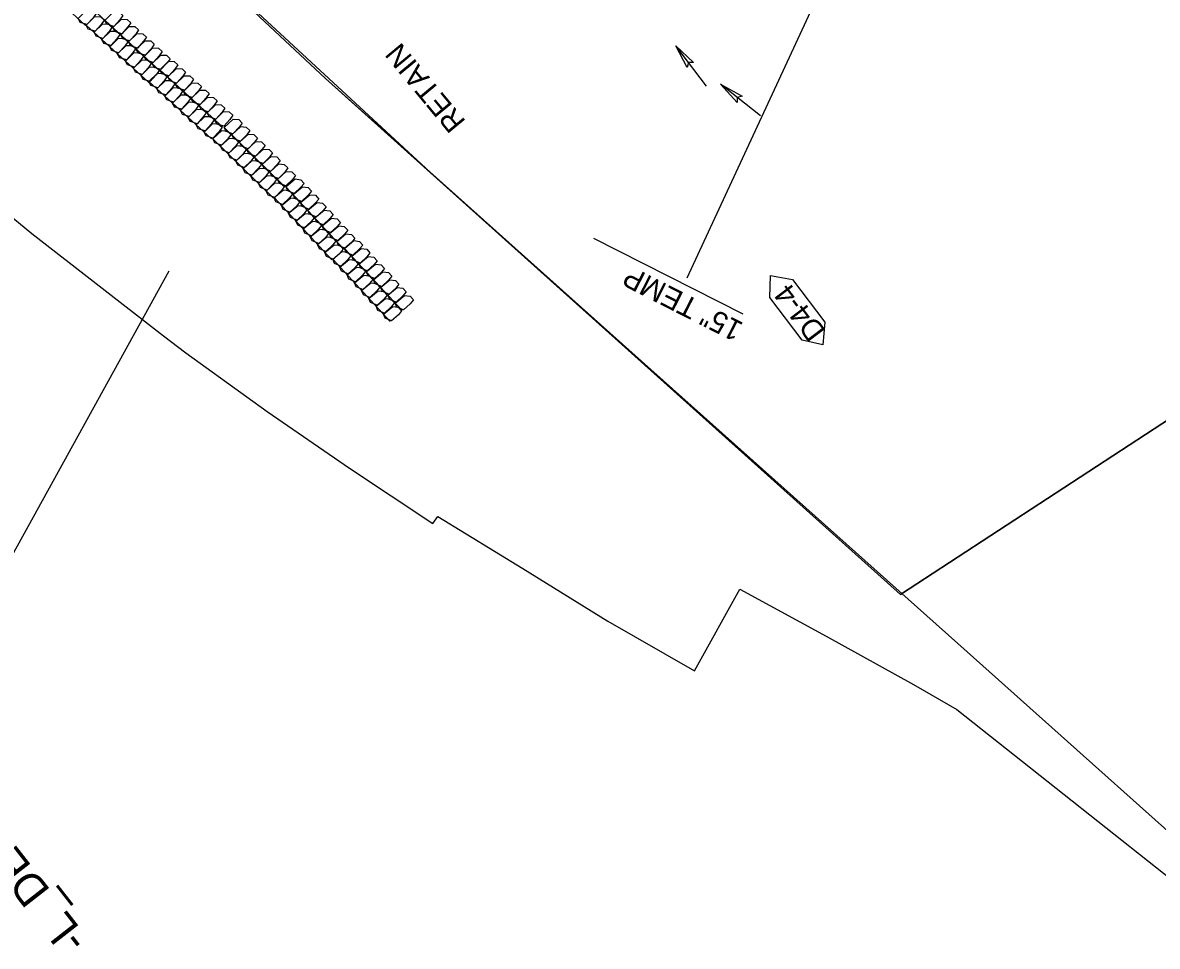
# Model space of a CAD drawing. Extents: x 465700 to 483515, y 488970 to 507540.
# Drawn here: x 476627.3 to 476894.9, y 500472.6 to 500690.3 of the extents above; entities that cross this region are included whole.
import ezdxf

# ---------------------------------------------------------------- set-up
doc = ezdxf.new("R2010")
doc.units = 0
for name, color, linetype in [('Exist Plan Preparation Watershed Blue', 7, 'Continuous'), ('Prop Drainage Structure Box Number Symbol CELL', 7, 'Continuous'), ('Prop Drainage Structure Pipe Collar Label', 7, 'Continuous'), ('Prop Drainage Structure Pipe Side Drain 15in', 7, 'Continuous'), ('Prop Drainage Structure Pipe Side Drain 15in Label', 7, 'Continuous'), ('Prop Erosion Embankment Toe Protection CELL', 7, 'Continuous'), ('Prop Plan Preparation Grade to Drain Arrows CELL', 7, 'Continuous'), ('Prop Plan Preparation Sag', 7, 'Continuous'), ('Prop Plan Preparation Sag Label', 7, 'Continuous')]:
    doc.layers.add(name, color=color, linetype=linetype)

msp = doc.modelspace()

# ---------------------------------------------------------------- linework, layer by layer
at = {"layer": 'Exist Plan Preparation Watershed Blue'}
for points in [[(476921.2, 501693.96), (476873.97, 501665.49), (476797.54, 501630.58), (476778.04, 501586.57), (476684.08, 501524.02), (476617.13, 501430.2), (476608.09, 501344.67), (476632.2, 501297.34), (476652.85, 501202.84), (476684.48, 501113.94), (476686.07, 501079.86), (476666.3, 501048.93), (476630.01, 501028.21), (476577.87, 501021.26), (476528.03, 501006.59), (476466.6, 500992.22), (476420.26, 500966.99), (476486.96, 500889.51), (476555.03, 500816.27), (476625.62, 500745.44), (476698.65, 500677.13), (476726.48, 500652.21), (476834.31, 500555.52), (476965.29, 500641)], [(476922.43, 500477.32), (476847.82, 500543.91), (476773.22, 500610.51), (476698.65, 500677.13), (476625.62, 500745.44), (476555.03, 500816.27), (476486.96, 500889.51), (476420.26, 500966.99), (476358.7, 501042.92), (476298.67, 501122.89), (476241.47, 501204.91)], [(476965.29, 500641), (476834.31, 500555.52), (476726.48, 500652.21), (476625.62, 500745.44), (476555.03, 500816.27), (476486.96, 500889.51), (476420.26, 500966.99), (476358.7, 501042.92), (476298.67, 501122.89), (476241.47, 501204.91)], [(476537.67, 500723.12), (476574.27, 500687.93), (476600.68, 500664.31), (476629.44, 500640.58), (476660.48, 500616.5), (476665.75, 500612.5), (476684.89, 500598.68), (476704.31, 500585.26), (476724.01, 500572.25), (476725.16, 500573.92), (476745.2, 500561.65), (476765.23, 500549.24), (476785.68, 500537.54), (476796.4, 500556.75), (476816.75, 500545.66), (476837.37, 500534.26), (476847.59, 500528.4), (476917.86, 500472.75)]]:
    msp.add_lwpolyline(points, dxfattribs=at)
at = {"layer": 'Prop Drainage Structure Box Number Symbol CELL'}
msp.add_lwpolyline([(476811.1, 500615.46), (476803.49, 500625.51), (476803.6, 500630.74), (476808.83, 500629.75), (476816.44, 500619.7), (476816, 500614.35), (476811.1, 500615.46)], dxfattribs=at)
at = {"layer": 'Prop Drainage Structure Pipe Side Drain 15in'}
msp.add_line((476797.15, 500621.56), (476761.98, 500639.45), dxfattribs=at)
at = {"layer": 'Prop Erosion Embankment Toe Protection CELL'}
for p, q in [((476627.34, 500703.2), (476642.1, 500689.7)), ((476644.8, 500692.56), (476659.56, 500679.06)), ((476642.24, 500689.75), (476657, 500676.26)), ((476659.62, 500679.23), (476674.38, 500665.73)), ((476657.05, 500676.42), (476671.81, 500662.92)), ((476674.77, 500665.65), (476689.05, 500651.65)), ((476672.11, 500662.94), (476686.39, 500648.93)), ((476689.36, 500651.65), (476702.95, 500636.98)), ((476686.57, 500649.07), (476700.16, 500634.4)), ((476703.16, 500637.11), (476716.75, 500622.43)), ((476700.37, 500634.53), (476713.96, 500619.85))]:
    msp.add_line(p, q, dxfattribs=at)
for points in [[(476644.56, 500692.46), (476643.86, 500691.48), (476642.41, 500689.89), (476640.83, 500690.39), (476640.33, 500691.32), (476642.36, 500693.32), (476643.67, 500693.27), (476644.56, 500692.46)], [(476650.88, 500692.02), (476650.2, 500691.01), (476648.75, 500689.43), (476647.15, 500689.94), (476646.65, 500690.87), (476648.7, 500692.86), (476650.03, 500692.79), (476650.88, 500692.02)], [(476646.47, 500690.9), (476645.77, 500689.91), (476644.32, 500688.33), (476642.74, 500688.82), (476642.24, 500689.75), (476644.27, 500691.76), (476645.6, 500691.69), (476646.47, 500690.9)], [(476648.32, 500689.21), (476647.64, 500688.21), (476646.18, 500686.62), (476644.59, 500687.13), (476644.08, 500688.07), (476646.14, 500690.05), (476647.47, 500689.99), (476648.32, 500689.21)], [(476652.74, 500690.31), (476652.06, 500689.31), (476650.61, 500687.72), (476649.01, 500688.23), (476648.51, 500689.17), (476650.57, 500691.15), (476651.88, 500691.1), (476652.74, 500690.31)], [(476650.18, 500687.51), (476649.5, 500686.5), (476648.05, 500684.92), (476646.45, 500685.43), (476645.95, 500686.36), (476648, 500688.35), (476649.31, 500688.3), (476650.18, 500687.51)], [(476654.61, 500688.61), (476653.91, 500687.62), (476652.46, 500686.03), (476650.88, 500686.53), (476650.38, 500687.46), (476652.41, 500689.46), (476653.72, 500689.42), (476654.61, 500688.61)], [(476656.45, 500686.92), (476655.75, 500685.93), (476654.3, 500684.35), (476652.72, 500684.84), (476652.22, 500685.78), (476654.25, 500687.78), (476655.58, 500687.71), (476656.45, 500686.92)], [(476652.04, 500685.8), (476651.34, 500684.82), (476649.89, 500683.23), (476648.31, 500683.73), (476647.81, 500684.66), (476649.85, 500686.66), (476651.16, 500686.61), (476652.04, 500685.8)], [(476653.89, 500684.12), (476653.19, 500683.13), (476651.74, 500681.54), (476650.16, 500682.04), (476649.66, 500682.97), (476651.69, 500684.97), (476653.02, 500684.91), (476653.89, 500684.12)], [(476658.3, 500685.23), (476657.62, 500684.23), (476656.16, 500682.64), (476654.57, 500683.15), (476654.06, 500684.09), (476656.12, 500686.07), (476657.45, 500686.01), (476658.3, 500685.23)], [(476660.16, 500683.53), (476659.48, 500682.52), (476658.03, 500680.94), (476656.43, 500681.45), (476655.93, 500682.38), (476657.98, 500684.37), (476659.29, 500684.32), (476660.16, 500683.53)], [(476655.73, 500682.43), (476655.05, 500681.42), (476653.6, 500679.84), (476652, 500680.35), (476651.5, 500681.28), (476653.55, 500683.27), (476654.88, 500683.2), (476655.73, 500682.43)], [(476657.59, 500680.72), (476656.91, 500679.72), (476655.46, 500678.13), (476653.86, 500678.65), (476653.36, 500679.58), (476655.42, 500681.56), (476656.73, 500681.52), (476657.59, 500680.72)], [(476662.02, 500681.82), (476661.32, 500680.84), (476659.87, 500679.25), (476658.29, 500679.75), (476657.79, 500680.68), (476659.83, 500682.68), (476661.14, 500682.63), (476662.02, 500681.82)], [(476659.46, 500679.02), (476658.76, 500678.03), (476657.31, 500676.45), (476655.73, 500676.94), (476655.23, 500677.88), (476657.26, 500679.88), (476658.57, 500679.83), (476659.46, 500679.02)], [(476663.85, 500680.37), (476663.15, 500679.38), (476661.7, 500677.8), (476660.12, 500678.29), (476659.62, 500679.23), (476661.65, 500681.23), (476662.98, 500681.16), (476663.85, 500680.37)], [(476665.69, 500678.68), (476665.01, 500677.68), (476663.56, 500676.09), (476661.97, 500676.61), (476661.46, 500677.54), (476663.52, 500679.52), (476664.85, 500679.46), (476665.69, 500678.68)], [(476661.29, 500677.57), (476660.59, 500676.58), (476659.13, 500674.99), (476657.56, 500675.49), (476657.05, 500676.42), (476659.09, 500678.43), (476660.42, 500678.36), (476661.29, 500677.57)], [(476663.13, 500675.88), (476662.45, 500674.88), (476661, 500673.29), (476659.4, 500673.8), (476658.9, 500674.74), (476660.95, 500676.72), (476662.28, 500676.66), (476663.13, 500675.88)], [(476667.56, 500676.98), (476666.88, 500675.98), (476665.43, 500674.39), (476663.83, 500674.9), (476663.33, 500675.84), (476665.38, 500677.82), (476666.69, 500677.77), (476667.56, 500676.98)], [(476669.42, 500675.28), (476668.72, 500674.29), (476667.27, 500672.7), (476665.69, 500673.2), (476665.19, 500674.13), (476667.22, 500676.13), (476668.54, 500676.09), (476669.42, 500675.28)], [(476664.99, 500674.18), (476664.31, 500673.17), (476662.86, 500671.59), (476661.26, 500672.1), (476660.76, 500673.03), (476662.81, 500675.02), (476664.13, 500674.97), (476664.99, 500674.18)], [(476671.27, 500673.59), (476670.57, 500672.6), (476669.12, 500671.02), (476667.54, 500671.51), (476667.03, 500672.44), (476669.07, 500674.45), (476670.4, 500674.38), (476671.27, 500673.59)], [(476666.86, 500672.47), (476666.16, 500671.49), (476664.71, 500669.9), (476663.13, 500670.39), (476662.62, 500671.33), (476664.66, 500673.33), (476665.97, 500673.28), (476666.86, 500672.47)], [(476668.7, 500670.78), (476668, 500669.8), (476666.55, 500668.21), (476664.97, 500668.71), (476664.47, 500669.64), (476666.5, 500671.64), (476667.83, 500671.58), (476668.7, 500670.78)], [(476673.11, 500671.9), (476672.43, 500670.9), (476670.98, 500669.31), (476669.38, 500669.82), (476668.88, 500670.76), (476670.93, 500672.74), (476672.26, 500672.68), (476673.11, 500671.9)], [(476674.97, 500670.2), (476674.29, 500669.19), (476672.84, 500667.61), (476671.24, 500668.12), (476670.74, 500669.05), (476672.79, 500671.04), (476674.11, 500670.99), (476674.97, 500670.2)], [(476670.55, 500669.1), (476669.86, 500668.09), (476668.41, 500666.51), (476666.82, 500667.02), (476666.31, 500667.95), (476668.37, 500669.94), (476669.7, 500669.87), (476670.55, 500669.1)], [(476672.41, 500667.39), (476671.73, 500666.39), (476670.28, 500664.8), (476668.68, 500665.32), (476668.18, 500666.25), (476670.23, 500668.23), (476671.54, 500668.19), (476672.41, 500667.39)], [(476676.84, 500668.49), (476676.14, 500667.51), (476674.69, 500665.92), (476673.11, 500666.42), (476672.61, 500667.35), (476674.64, 500669.35), (476675.95, 500669.3), (476676.84, 500668.49)], [(476674.27, 500665.69), (476673.57, 500664.7), (476672.12, 500663.12), (476670.54, 500663.61), (476670.04, 500664.54), (476672.07, 500666.55), (476673.39, 500666.5), (476674.27, 500665.69)], [(476679.04, 500666.65), (476678.31, 500665.69), (476676.8, 500664.15), (476675.24, 500664.7), (476674.77, 500665.65), (476676.87, 500667.58), (476678.2, 500667.47), (476679.04, 500666.65)], [(476680.82, 500664.9), (476680.11, 500663.92), (476678.6, 500662.38), (476677.02, 500662.95), (476676.56, 500663.9), (476678.68, 500665.81), (476680, 500665.7), (476680.82, 500664.9)], [(476676.38, 500663.94), (476675.65, 500662.97), (476674.14, 500661.44), (476672.58, 500661.99), (476672.11, 500662.94), (476674.21, 500664.87), (476675.54, 500664.76), (476676.38, 500663.94)], [(476678.16, 500662.19), (476677.45, 500661.21), (476675.94, 500659.67), (476674.36, 500660.24), (476673.89, 500661.19), (476676.02, 500663.1), (476677.34, 500662.99), (476678.16, 500662.19)], [(476682.63, 500663.13), (476681.91, 500662.15), (476680.41, 500660.62), (476678.83, 500661.18), (476678.36, 500662.13), (476680.48, 500664.05), (476681.79, 500663.95), (476682.63, 500663.13)], [(476679.97, 500660.42), (476679.25, 500659.44), (476677.74, 500657.9), (476676.17, 500658.47), (476675.7, 500659.42), (476677.82, 500661.33), (476679.13, 500661.24), (476679.97, 500660.42)], [(476684.43, 500661.36), (476683.7, 500660.4), (476682.19, 500658.86), (476680.63, 500659.42), (476680.16, 500660.37), (476682.26, 500662.3), (476683.57, 500662.2), (476684.43, 500661.36)], [(476686.21, 500659.61), (476685.48, 500658.65), (476683.97, 500657.11), (476682.41, 500657.66), (476681.94, 500658.61), (476684.05, 500660.54), (476685.37, 500660.43), (476686.21, 500659.61)], [(476681.77, 500658.65), (476681.03, 500657.69), (476679.53, 500656.15), (476677.97, 500656.7), (476677.5, 500657.65), (476679.6, 500659.58), (476680.91, 500659.49), (476681.77, 500658.65)], [(476683.55, 500656.9), (476682.82, 500655.94), (476681.31, 500654.4), (476679.75, 500654.95), (476679.28, 500655.9), (476681.39, 500657.83), (476682.71, 500657.72), (476683.55, 500656.9)], [(476688, 500657.86), (476687.28, 500656.88), (476685.78, 500655.35), (476684.2, 500655.91), (476683.73, 500656.86), (476685.85, 500658.78), (476687.18, 500658.66), (476688, 500657.86)], [(476685.34, 500655.15), (476684.62, 500654.17), (476683.12, 500652.63), (476681.54, 500653.2), (476681.07, 500654.15), (476683.19, 500656.06), (476684.52, 500655.95), (476685.34, 500655.15)], [(476689.8, 500656.09), (476689.09, 500655.11), (476687.58, 500653.58), (476686, 500654.15), (476685.53, 500655.1), (476687.65, 500657.01), (476688.96, 500656.91), (476689.8, 500656.09)], [(476691.6, 500654.32), (476690.87, 500653.36), (476689.36, 500651.83), (476687.8, 500652.38), (476687.33, 500653.33), (476689.44, 500655.26), (476690.75, 500655.16), (476691.6, 500654.32)], [(476687.14, 500653.38), (476686.42, 500652.4), (476684.92, 500650.86), (476683.34, 500651.43), (476682.87, 500652.38), (476684.99, 500654.3), (476686.3, 500654.2), (476687.14, 500653.38)], [(476688.94, 500651.61), (476688.21, 500650.65), (476686.7, 500649.11), (476685.14, 500649.66), (476684.67, 500650.62), (476686.78, 500652.54), (476688.09, 500652.45), (476688.94, 500651.61)], [(476693.67, 500652.44), (476692.89, 500651.52), (476691.31, 500650.06), (476689.78, 500650.68), (476689.36, 500651.65), (476691.55, 500653.48), (476692.87, 500653.3), (476693.67, 500652.44)], [(476690.88, 500649.86), (476690.1, 500648.93), (476688.53, 500647.47), (476686.99, 500648.1), (476686.57, 500649.07), (476688.76, 500650.9), (476690.08, 500650.72), (476690.88, 500649.86)], [(476695.37, 500650.61), (476694.61, 500649.66), (476693.03, 500648.2), (476691.48, 500648.85), (476691.06, 500649.82), (476693.27, 500651.63), (476694.59, 500651.45), (476695.37, 500650.61)], [(476697.08, 500648.75), (476696.32, 500647.81), (476694.75, 500646.35), (476693.2, 500646.99), (476692.77, 500647.96), (476694.98, 500649.77), (476696.29, 500649.62), (476697.08, 500648.75)], [(476692.58, 500648.03), (476691.82, 500647.08), (476690.24, 500645.62), (476688.69, 500646.26), (476688.27, 500647.24), (476690.48, 500649.04), (476691.8, 500648.87), (476692.58, 500648.03)], [(476694.3, 500646.17), (476693.54, 500645.23), (476691.96, 500643.77), (476690.41, 500644.41), (476689.99, 500645.38), (476692.2, 500647.19), (476693.5, 500647.03), (476694.3, 500646.17)], [(476698.8, 500646.9), (476698.02, 500645.98), (476696.44, 500644.52), (476694.91, 500645.14), (476694.49, 500646.11), (476696.68, 500647.94), (476697.98, 500647.78), (476698.8, 500646.9)], [(476696.01, 500644.32), (476695.23, 500643.39), (476693.66, 500641.93), (476692.12, 500642.56), (476691.7, 500643.53), (476693.89, 500645.36), (476695.2, 500645.2), (476696.01, 500644.32)], [(476700.5, 500645.07), (476699.72, 500644.14), (476698.14, 500642.68), (476696.61, 500643.31), (476696.19, 500644.28), (476698.38, 500646.1), (476699.7, 500645.93), (476700.5, 500645.07)], [(476702.2, 500643.23), (476701.44, 500642.29), (476699.86, 500640.83), (476698.31, 500641.47), (476697.89, 500642.44), (476700.1, 500644.25), (476701.42, 500644.08), (476702.2, 500643.23)], [(476697.71, 500642.49), (476696.93, 500641.56), (476695.36, 500640.1), (476693.82, 500640.72), (476693.4, 500641.7), (476695.59, 500643.52), (476696.91, 500643.35), (476697.71, 500642.49)], [(476699.41, 500640.65), (476698.65, 500639.71), (476697.07, 500638.25), (476695.52, 500638.89), (476695.1, 500639.86), (476697.31, 500641.67), (476698.63, 500641.5), (476699.41, 500640.65)], [(476703.91, 500641.38), (476703.15, 500640.44), (476701.57, 500638.98), (476700.02, 500639.62), (476699.6, 500640.59), (476701.81, 500642.4), (476703.12, 500642.24), (476703.91, 500641.38)], [(476701.13, 500638.8), (476700.36, 500637.86), (476698.79, 500636.39), (476697.24, 500637.04), (476696.81, 500638.01), (476699.02, 500639.82), (476700.33, 500639.66), (476701.13, 500638.8)], [(476705.63, 500639.53), (476704.85, 500638.6), (476703.27, 500637.14), (476701.74, 500637.77), (476701.32, 500638.74), (476703.51, 500640.57), (476704.81, 500640.41), (476705.63, 500639.53)], [(476707.47, 500637.9), (476706.69, 500636.97), (476705.11, 500635.51), (476703.58, 500636.14), (476703.16, 500637.11), (476705.35, 500638.94), (476706.67, 500638.76), (476707.47, 500637.9)], [(476702.84, 500636.95), (476702.06, 500636.02), (476700.49, 500634.56), (476698.95, 500635.19), (476698.53, 500636.16), (476700.72, 500637.98), (476702.03, 500637.83), (476702.84, 500636.95)], [(476704.68, 500635.32), (476703.9, 500634.39), (476702.32, 500632.93), (476700.79, 500633.56), (476700.37, 500634.53), (476702.56, 500636.35), (476703.88, 500636.18), (476704.68, 500635.32)], [(476709.17, 500636.06), (476708.41, 500635.12), (476706.83, 500633.66), (476705.28, 500634.3), (476704.86, 500635.27), (476707.07, 500637.08), (476708.39, 500636.91), (476709.17, 500636.06)], [(476706.38, 500633.48), (476705.62, 500632.54), (476704.04, 500631.08), (476702.49, 500631.72), (476702.07, 500632.69), (476704.28, 500634.5), (476705.6, 500634.33), (476706.38, 500633.48)], [(476710.88, 500634.21), (476710.12, 500633.27), (476708.54, 500631.81), (476706.99, 500632.45), (476706.57, 500633.42), (476708.78, 500635.23), (476710.08, 500635.07), (476710.88, 500634.21)], [(476712.6, 500632.36), (476711.82, 500631.43), (476710.24, 500629.97), (476708.71, 500630.6), (476708.29, 500631.57), (476710.48, 500633.4), (476711.78, 500633.24), (476712.6, 500632.36)], [(476708.09, 500631.63), (476707.33, 500630.69), (476705.76, 500629.22), (476704.21, 500629.87), (476703.78, 500630.84), (476705.99, 500632.65), (476707.3, 500632.49), (476708.09, 500631.63)], [(476709.81, 500629.78), (476709.03, 500628.85), (476707.45, 500627.39), (476705.92, 500628.02), (476705.5, 500628.99), (476707.69, 500630.81), (476708.99, 500630.66), (476709.81, 500629.78)], [(476714.3, 500630.52), (476713.52, 500629.6), (476711.94, 500628.14), (476710.41, 500628.76), (476709.99, 500629.73), (476712.18, 500631.56), (476713.5, 500631.39), (476714.3, 500630.52)], [(476711.51, 500627.94), (476710.73, 500627.02), (476709.15, 500625.56), (476707.62, 500626.18), (476707.2, 500627.15), (476709.39, 500628.98), (476710.71, 500628.8), (476711.51, 500627.94)], [(476716, 500628.69), (476715.23, 500627.75), (476713.66, 500626.29), (476712.11, 500626.93), (476711.68, 500627.9), (476713.89, 500629.71), (476715.21, 500629.53), (476716, 500628.69)], [(476713.21, 500626.11), (476712.45, 500625.16), (476710.87, 500623.7), (476709.32, 500624.35), (476708.9, 500625.32), (476711.11, 500627.13), (476712.43, 500626.95), (476713.21, 500626.11)], [(476714.92, 500624.26), (476714.16, 500623.31), (476712.58, 500621.85), (476711.03, 500622.49), (476710.61, 500623.47), (476712.82, 500625.27), (476714.12, 500625.12), (476714.92, 500624.26)], [(476717.71, 500626.84), (476716.95, 500625.89), (476715.37, 500624.43), (476713.82, 500625.08), (476713.4, 500626.05), (476715.61, 500627.86), (476716.91, 500627.7), (476717.71, 500626.84)], [(476719.43, 500624.99), (476718.65, 500624.06), (476717.07, 500622.6), (476715.54, 500623.22), (476715.12, 500624.2), (476717.31, 500626.02), (476718.61, 500625.87), (476719.43, 500624.99)], [(476716.64, 500622.4), (476715.86, 500621.48), (476714.28, 500620.02), (476712.75, 500620.64), (476712.33, 500621.61), (476714.52, 500623.44), (476715.82, 500623.28), (476716.64, 500622.4)]]:
    msp.add_lwpolyline(points, dxfattribs=at)
at = {"layer": 'Prop Plan Preparation Grade to Drain Arrows CELL'}
for p, q in [((476788.54, 500675.33), (476781.29, 500684.9)), ((476801.28, 500668.37), (476791.85, 500675.79))]:
    msp.add_line(p, q, dxfattribs=at)
for points in [[(476783.98, 500679.77), (476781.29, 500684.9), (476785.5, 500680.92), (476784.31, 500680.91)], [(476795.75, 500671.51), (476791.85, 500675.79), (476796.92, 500673), (476795.78, 500672.7)]]:
    msp.add_lwpolyline(points, close=True, dxfattribs=at)
at = {"layer": 'Prop Plan Preparation Sag'}
for p, q in [((476783.98, 500630.18), (476846.88, 500765.92)), ((476661.71, 500631.77), (476604.66, 500528.38))]:
    msp.add_line(p, q, dxfattribs=at)

# ---------------------------------------------------------------- texts
at = {"layer": 'Prop Drainage Structure Box Number Symbol CELL'}
msp.add_text('D4-4', height=5, rotation=127.1208, dxfattribs=at).set_placement((476816.84, 500617.65))
at = {"layer": 'Prop Drainage Structure Pipe Collar Label'}
msp.add_text('RETAIN', height=5, rotation=129.6265, dxfattribs=at).set_placement((476731.93, 500667.05))
at = {"layer": 'Prop Drainage Structure Pipe Side Drain 15in Label'}
msp.add_text('15" TEMP', height=5, rotation=153.0466, dxfattribs=at).set_placement((476797.51, 500619.39))
at = {"layer": 'Prop Plan Preparation Sag Label'}
msp.add_text('-L_DET4- STA. 14+31.93', height=7.5, rotation=128.006, dxfattribs=at).set_placement((476642.93, 500474.25))

doc.saveas('drawing.dxf')
